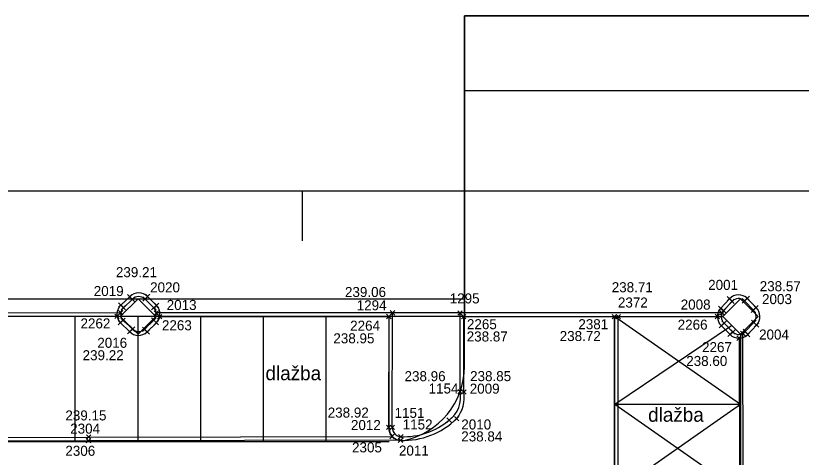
# Model space of a CAD drawing. Extents: x -264222 to -263676, y -1242344 to -1242060.
# Drawn here: x -264149.44 to -264118.14, y -1242197.1 to -1242179.48 of the extents above; entities that cross this region are included whole.
import ezdxf

# ---------------------------------------------------------------- set-up
doc = ezdxf.new("R2010")
doc.units = 0
for name, color, linetype in [('BODY_CISLO', 7, 'Continuous'), ('BODY_SYMBOL', 7, 'Continuous'), ('BODY_VYSKA', 7, 'Continuous'), ('KOORDINACNA_SITUACIA_DSP', 7, 'Continuous'), ('POPIS', 7, 'Continuous'), ('PROJEKT_DRS_OBRUBNIKY_KOMUNIKACIE', 7, 'Continuous'), ('PROJEKT_DRS_TDZ_VODOROVNE', 7, 'Continuous'), ('RAM_NA_TLAC_8xA4_1-200', 7, 'Continuous'), ('SO_20-3_OBRUBNIKY_DOLNA_HRANA', 7, 'Continuous'), ('SO_20-3_OBRUBNIKY_HORNA_HRANA', 7, 'Continuous')]:
    doc.layers.add(name, color=color, linetype=linetype)

msp = doc.modelspace()

# ---------------------------------------------------------------- linework, layer by layer
at = {"layer": 'BODY_SYMBOL'}
for p, q in [((-264144.989, -1242190.779), (-264144.813, -1242190.603)), ((-264144.813, -1242190.779), (-264144.989, -1242190.603)), ((-264144.276, -1242190.772), (-264144.1, -1242190.596)), ((-264144.1, -1242190.772), (-264144.276, -1242190.596)), ((-264144.884, -1242190.882), (-264144.708, -1242190.706)), ((-264144.708, -1242190.882), (-264144.884, -1242190.706)), ((-264144.38, -1242190.87), (-264144.204, -1242190.694)), ((-264144.204, -1242190.87), (-264144.38, -1242190.694)), ((-264121.093, -1242190.859), (-264120.917, -1242190.683)), ((-264120.917, -1242190.859), (-264121.093, -1242190.683)), ((-264120.993, -1242190.968), (-264120.817, -1242190.792)), ((-264120.817, -1242190.968), (-264120.993, -1242190.792)), ((-264120.494, -1242190.945), (-264120.318, -1242190.769)), ((-264120.318, -1242190.945), (-264120.494, -1242190.769)), ((-264120.384, -1242190.849), (-264120.208, -1242190.673)), ((-264120.208, -1242190.849), (-264120.384, -1242190.673)), ((-264145.346, -1242191.417), (-264145.17, -1242191.241)), ((-264145.17, -1242191.417), (-264145.346, -1242191.241)), ((-264145.341, -1242191.113), (-264145.165, -1242190.937)), ((-264145.165, -1242191.113), (-264145.341, -1242190.937)), ((-264145.238, -1242191.221), (-264145.062, -1242191.045)), ((-264145.062, -1242191.221), (-264145.238, -1242191.045)), ((-264144.028, -1242191.218), (-264143.852, -1242191.042)), ((-264143.852, -1242191.218), (-264144.028, -1242191.042)), ((-264143.919, -1242191.129), (-264143.743, -1242190.953)), ((-264143.743, -1242191.129), (-264143.919, -1242190.953)), ((-264121.442, -1242191.24), (-264121.266, -1242191.064)), ((-264121.266, -1242191.24), (-264121.442, -1242191.064)), ((-264121.328, -1242191.336), (-264121.152, -1242191.16)), ((-264121.152, -1242191.336), (-264121.328, -1242191.16)), ((-264120.142, -1242191.318), (-264119.966, -1242191.142)), ((-264119.966, -1242191.318), (-264120.142, -1242191.142)), ((-264120.033, -1242191.215), (-264119.857, -1242191.039)), ((-264119.857, -1242191.215), (-264120.033, -1242191.039)), ((-264145.491, -1242191.564), (-264145.315, -1242191.388)), ((-264145.315, -1242191.564), (-264145.491, -1242191.388)), ((-264145.252, -1242191.718), (-264145.076, -1242191.542)), ((-264145.076, -1242191.718), (-264145.252, -1242191.542)), ((-264144.029, -1242191.716), (-264143.853, -1242191.54)), ((-264143.853, -1242191.716), (-264144.029, -1242191.54)), ((-264143.928, -1242191.426), (-264143.752, -1242191.25)), ((-264143.752, -1242191.426), (-264143.928, -1242191.25)), ((-264143.794, -1242191.572), (-264143.618, -1242191.396)), ((-264143.618, -1242191.572), (-264143.794, -1242191.396)), ((-264134.664, -1242191.569), (-264134.488, -1242191.393)), ((-264134.488, -1242191.569), (-264134.664, -1242191.393)), ((-264134.518, -1242191.422), (-264134.342, -1242191.246)), ((-264134.342, -1242191.422), (-264134.518, -1242191.246)), ((-264131.826, -1242191.425), (-264131.65, -1242191.249)), ((-264131.65, -1242191.425), (-264131.826, -1242191.249)), ((-264131.68, -1242191.574), (-264131.504, -1242191.398)), ((-264131.504, -1242191.574), (-264131.68, -1242191.398)), ((-264125.678, -1242191.572), (-264125.502, -1242191.396)), ((-264125.502, -1242191.572), (-264125.678, -1242191.396)), ((-264125.523, -1242191.572), (-264125.347, -1242191.396)), ((-264125.347, -1242191.572), (-264125.523, -1242191.396)), ((-264121.573, -1242191.57), (-264121.397, -1242191.394)), ((-264121.397, -1242191.57), (-264121.573, -1242191.394)), ((-264121.386, -1242191.425), (-264121.21, -1242191.249)), ((-264121.21, -1242191.425), (-264121.386, -1242191.249)), ((-264145.361, -1242191.818), (-264145.185, -1242191.642)), ((-264145.185, -1242191.818), (-264145.361, -1242191.642)), ((-264143.927, -1242191.819), (-264143.751, -1242191.643)), ((-264143.751, -1242191.819), (-264143.927, -1242191.643)), ((-264121.422, -1242191.934), (-264121.246, -1242191.758)), ((-264121.246, -1242191.934), (-264121.422, -1242191.758)), ((-264121.306, -1242191.836), (-264121.13, -1242191.66)), ((-264121.13, -1242191.836), (-264121.306, -1242191.66)), ((-264120.122, -1242191.808), (-264119.946, -1242191.632)), ((-264119.946, -1242191.808), (-264120.122, -1242191.632)), ((-264120.016, -1242191.913), (-264119.84, -1242191.737)), ((-264119.84, -1242191.913), (-264120.016, -1242191.737)), ((-264144.995, -1242192.171), (-264144.819, -1242191.995)), ((-264144.819, -1242192.171), (-264144.995, -1242191.995)), ((-264144.877, -1242192.074), (-264144.701, -1242191.898)), ((-264144.701, -1242192.074), (-264144.877, -1242191.898)), ((-264144.397, -1242192.079), (-264144.221, -1242191.903)), ((-264144.221, -1242192.079), (-264144.397, -1242191.903)), ((-264144.294, -1242192.185), (-264144.118, -1242192.009)), ((-264144.118, -1242192.185), (-264144.294, -1242192.009)), ((-264121.072, -1242192.285), (-264120.896, -1242192.109)), ((-264120.896, -1242192.285), (-264121.072, -1242192.109)), ((-264120.955, -1242192.19), (-264120.779, -1242192.014)), ((-264120.779, -1242192.19), (-264120.955, -1242192.014)), ((-264120.563, -1242192.247), (-264120.387, -1242192.071)), ((-264120.387, -1242192.247), (-264120.563, -1242192.071)), ((-264120.463, -1242192.168), (-264120.287, -1242191.992)), ((-264120.287, -1242192.168), (-264120.463, -1242191.992)), ((-264120.365, -1242192.288), (-264120.189, -1242192.112)), ((-264120.189, -1242192.288), (-264120.365, -1242192.112)), ((-264120.712, -1242192.434), (-264120.536, -1242192.258)), ((-264120.536, -1242192.434), (-264120.712, -1242192.258)), ((-264131.827, -1242194.565), (-264131.651, -1242194.389)), ((-264131.651, -1242194.565), (-264131.827, -1242194.389)), ((-264131.678, -1242194.582), (-264131.502, -1242194.406)), ((-264131.502, -1242194.582), (-264131.678, -1242194.406)), ((-264132.26, -1242195.703), (-264132.084, -1242195.527)), ((-264132.084, -1242195.703), (-264132.26, -1242195.527)), ((-264131.963, -1242195.64), (-264131.787, -1242195.464)), ((-264131.787, -1242195.64), (-264131.963, -1242195.464)), ((-264134.674, -1242195.993), (-264134.498, -1242195.817)), ((-264134.498, -1242195.993), (-264134.674, -1242195.817)), ((-264134.526, -1242195.994), (-264134.35, -1242195.818)), ((-264134.35, -1242195.994), (-264134.526, -1242195.818)), ((-264146.62, -1242196.381), (-264146.444, -1242196.205)), ((-264146.444, -1242196.381), (-264146.62, -1242196.205)), ((-264134.536, -1242196.356), (-264134.36, -1242196.18)), ((-264134.36, -1242196.356), (-264134.536, -1242196.18)), ((-264134.186, -1242196.364), (-264134.01, -1242196.188)), ((-264134.01, -1242196.364), (-264134.186, -1242196.188)), ((-264146.629, -1242196.527), (-264146.453, -1242196.351)), ((-264146.453, -1242196.527), (-264146.629, -1242196.351)), ((-264134.199, -1242196.508), (-264134.023, -1242196.332)), ((-264134.023, -1242196.508), (-264134.199, -1242196.332))]:
    msp.add_line(p, q, dxfattribs=at)
at = {"layer": 'KOORDINACNA_SITUACIA_DSP'}
for p, q in [((-264131.568, -1242193.482), (-264131.568, -1242186.466)), ((-264131.568, -1242186.466), (-264131.568, -1242191.482)), ((-264170.162, -1242190.775), (-264131.568, -1242190.775)), ((-264131.568, -1242191.482), (-264172.558, -1242191.482)), ((-264134.568, -1242191.482), (-264169.568, -1242191.482)), ((-264134.568, -1242195.932), (-264134.568, -1242191.482)), ((-264120.568, -1242192.189), (-264120.568, -1242209.775))]:
    msp.add_line(p, q, dxfattribs=at)
for points in [[(-264144.568, -1242190.775), (-264143.861, -1242191.482), (-264144.568, -1242192.189), (-264145.275, -1242191.482)], [(-264120.568, -1242190.775), (-264119.861, -1242191.482), (-264120.568, -1242192.189), (-264121.275, -1242191.482)]]:
    msp.add_lwpolyline(points, close=True, dxfattribs=at)
msp.add_lwpolyline([(-264143.861, -1242191.482), (-264143.861, -1242191.482), (-264144.568, -1242192.189), (-264145.275, -1242191.482)], dxfattribs=at)
for centre, radius, start, end in [((-264134.568, -1242193.482), 3, 281.537, 0), ((-264134.068, -1242195.932), 0.5, 180, 281.537)]:
    msp.add_arc(centre, radius, start, end, dxfattribs=at)
at = {"layer": 'PROJEKT_DRS_OBRUBNIKY_KOMUNIKACIE'}
for p, q in [((-263959.468, -1242179.482), (-264131.568, -1242179.482)), ((-264131.568, -1242193.482), (-264131.568, -1242179.482)), ((-264077.23, -1242179.482), (-264131.568, -1242179.482)), ((-264131.568, -1242179.482), (-264131.568, -1242191.482)), ((-264131.568, -1242179.482), (-263959.468, -1242179.482)), ((-264045.204, -1242182.482), (-264131.568, -1242182.482)), ((-264170.162, -1242190.775), (-264131.568, -1242190.775)), ((-264131.568, -1242191.482), (-264172.558, -1242191.482)), ((-264134.568, -1242191.482), (-264169.568, -1242191.482)), ((-264134.568, -1242195.932), (-264134.568, -1242191.482)), ((-264131.568, -1242191.482), (-264121.275, -1242191.482)), ((-264125.568, -1242270.982), (-264125.568, -1242191.482)), ((-264120.568, -1242192.189), (-264120.568, -1242209.775)), ((-264134.568, -1242196.482), (-264170.068, -1242196.482))]:
    msp.add_line(p, q, dxfattribs=at)
for points in [[(-264144.568, -1242190.775), (-264143.861, -1242191.482), (-264144.568, -1242192.189), (-264145.275, -1242191.482), (-264144.568, -1242190.775)], [(-264120.568, -1242190.775), (-264119.861, -1242191.482), (-264120.568, -1242192.189), (-264121.275, -1242191.482), (-264120.568, -1242190.775)], [(-264143.861, -1242191.482), (-264144.568, -1242192.189), (-264145.275, -1242191.482)]]:
    msp.add_lwpolyline(points, dxfattribs=at)
for centre, radius, start, end in [((-264134.568, -1242193.482), 3, 281.537, 0), ((-264134.068, -1242195.932), 0.5, 180, 281.537)]:
    msp.add_arc(centre, radius, start, end, dxfattribs=at)
at = {"layer": 'PROJEKT_DRS_TDZ_VODOROVNE'}
for p, q in [((-264147.068, -1242196.482), (-264147.068, -1242191.482)), ((-264144.568, -1242196.482), (-264144.568, -1242191.482)), ((-264142.068, -1242196.482), (-264142.068, -1242191.482)), ((-264139.568, -1242196.482), (-264139.568, -1242191.482)), ((-264137.068, -1242196.482), (-264137.068, -1242191.482)), ((-264125.568, -1242191.482), (-264120.568, -1242194.982)), ((-264125.568, -1242194.982), (-264120.921, -1242191.836)), ((-264125.568, -1242194.982), (-264120.568, -1242194.982)), ((-264125.568, -1242194.982), (-264120.568, -1242198.482)), ((-264125.568, -1242198.482), (-264120.568, -1242194.982))]:
    msp.add_line(p, q, dxfattribs=at)
at = {"layer": 'RAM_NA_TLAC_8xA4_1-200'}
msp.add_line((-264138.03, -1242186.466), (-264138.03, -1242188.466), dxfattribs=at)
msp.add_lwpolyline([(-264222.03, -1242186.466), (-264054.03, -1242186.466), (-264054.03, -1242305.266), (-264222.03, -1242305.266)], close=True, dxfattribs=at)
at = {"layer": 'SO_20-3_OBRUBNIKY_DOLNA_HRANA'}
for p, q in [((-264145.253, -1242191.025), (-264144.901, -1242190.691)), ((-264144.188, -1242190.684), (-264143.831, -1242191.041)), ((-264121.354, -1242191.152), (-264121.005, -1242190.771)), ((-264120.296, -1242190.761), (-264119.945, -1242191.127)), ((-264153.705, -1242191.47), (-264145.403, -1242191.476)), ((-264144.907, -1242192.083), (-264145.273, -1242191.73)), ((-264143.839, -1242191.731), (-264144.206, -1242192.097)), ((-264120.984, -1242192.197), (-264121.334, -1242191.846)), ((-264119.928, -1242191.825), (-264120.277, -1242192.2)), ((-264120.624, -1242192.346), (-264120.576, -1242209.647))]:
    msp.add_line(p, q, dxfattribs=at)
for points in [[(-264143.706, -1242191.484), (-264134.576, -1242191.481), (-264134.586, -1242195.905)], [(-264131.59, -1242194.494), (-264131.592, -1242191.486), (-264121.485, -1242191.482)], [(-264125.573, -1242270.915), (-264125.578, -1242264.895), (-264125.575, -1242255.299), (-264125.581, -1242244.324), (-264125.582, -1242233.844), (-264125.584, -1242219.84), (-264125.593, -1242209.81), (-264125.59, -1242197.798), (-264125.59, -1242191.484)], [(-264125.429, -1242270.662), (-264125.437, -1242264.9), (-264125.431, -1242255.315), (-264125.435, -1242244.34), (-264125.439, -1242233.845), (-264125.44, -1242219.841), (-264125.448, -1242209.814), (-264125.447, -1242197.797), (-264125.435, -1242191.484)], [(-264134.111, -1242196.42), (-264146.541, -1242196.439), (-264159.053, -1242196.46), (-264170.082, -1242196.449)], [(-264169.718, -1242196.306), (-264159.062, -1242196.316), (-264146.532, -1242196.293), (-264134.448, -1242196.268)]]:
    msp.add_lwpolyline(points, dxfattribs=at)
for centre, major_axis, ratio, start_param, end_param in [((-264144.541, -1242191.035), (-0.422, -0.263), 0.999561, 3.365891, 4.96317), ((-264120.645, -1242191.116), (-0.299, 0.398), 0.999195, 4.861097, 6.446101), ((-264144.917, -1242191.387), (0.345, -0.354), 0.99993, 3.116184, 4.704475), ((-264144.191, -1242191.382), (-0.199, 0.454), 0.999498, 3.518922, 5.05719), ((-264120.987, -1242191.489), (-0.008, -0.498), 0.999493, 3.986167, 5.529115), ((-264120.286, -1242191.485), (0.366, 0.332), 0.999212, 4.786746, 6.357217), ((-264144.55, -1242191.732), (0.45, -0.222), 0.999046, 4.376126, 5.925508), ((-264120.629, -1242191.849), (0.492, -0.07), 0.999786, 4.058846, 5.64051), ((-264132.871, -1242194.716), (0.519, 1.193), 0.999825, 4.424596, 5.294154), ((-264133.978, -1242193.449), (1.173, -2.733), 0.999586, 5.832872, 6.663414), ((-264134.091, -1242195.924), (0.143, -0.475), 0.999359, 4.382247, 5.950366)]:
    msp.add_ellipse(centre, major_axis=major_axis, ratio=ratio, start_param=start_param, end_param=end_param, dxfattribs=at)
at = {"layer": 'SO_20-3_OBRUBNIKY_HORNA_HRANA'}
for p, q in [((-264145.15, -1242191.133), (-264144.796, -1242190.794)), ((-264144.292, -1242190.782), (-264143.94, -1242191.13)), ((-264120.905, -1242190.88), (-264121.24, -1242191.248)), ((-264120.054, -1242191.23), (-264120.406, -1242190.857)), ((-264153.851, -1242191.32), (-264145.258, -1242191.329)), ((-264134.43, -1242191.334), (-264143.84, -1242191.338)), ((-264134.438, -1242195.906), (-264134.43, -1242191.334)), ((-264131.738, -1242191.337), (-264134.43, -1242191.334)), ((-264131.739, -1242194.477), (-264131.738, -1242191.337)), ((-264121.298, -1242191.337), (-264131.738, -1242191.337)), ((-264144.789, -1242191.986), (-264145.164, -1242191.63)), ((-264143.941, -1242191.628), (-264144.309, -1242191.991)), ((-264120.867, -1242192.102), (-264121.218, -1242191.748)), ((-264120.034, -1242191.72), (-264120.375, -1242192.08)), ((-264120.432, -1242209.796), (-264120.475, -1242192.159))]:
    msp.add_line(p, q, dxfattribs=at)
for centre, major_axis, ratio, start_param, end_param in [((-264144.538, -1242191.045), (-0.315, -0.173), 0.999249, 3.457587, 5.009545), ((-264120.644, -1242191.112), (-0.018, -0.349), 0.999604, 2.442089, 4.03731), ((-264144.919, -1242191.388), (0.129, -0.32), 0.999189, 3.495291, 5.107355), ((-264144.191, -1242191.378), (-0.256, 0.243), 0.999863, 3.115121, 4.681209), ((-264120.288, -1242191.485), (0.177, 0.297), 0.998641, 4.503908, 6.079514), ((-264120.974, -1242191.487), (-0.005, -0.358), 0.99766, 3.996827, 5.544901), ((-264144.546, -1242191.729), (0.319, -0.151), 0.999204, 4.39641, 5.890386), ((-264120.631, -1242191.859), (0.338, -0.02), 0.999255, 4.002727, 5.632823), ((-264132.841, -1242194.709), (0.341, 1.074), 0.999027, 4.085727, 5.227258), ((-264133.993, -1242193.452), (2.311, -1.629), 0.99934, 5.28896, 6.025987), ((-264134.079, -1242195.917), (0.038, -0.357), 0.999322, 4.574758, 6.122971)]:
    msp.add_ellipse(centre, major_axis=major_axis, ratio=ratio, start_param=start_param, end_param=end_param, dxfattribs=at)

# ---------------------------------------------------------------- texts
at = {"layer": 'BODY_CISLO'}
for s, p in [('2019', (-264146.333, -1242190.665)), ('2020', (-264144.088, -1242190.517)), ('2001', (-264121.855, -1242190.42)), ('1295', (-264132.152, -1242190.96)), ('2003', (-264119.709, -1242190.986)), ('2013', (-264143.427, -1242191.22)), ('1294', (-264135.857, -1242191.234)), ('2372', (-264125.451, -1242191.123)), ('2008', (-264122.949, -1242191.205)), ('2262', (-264146.861, -1242191.957)), ('2263', (-264143.617, -1242192.031)), ('2264', (-264136.118, -1242192.047)), ('2265', (-264131.466, -1242191.988)), ('2381', (-264127.027, -1242191.989)), ('2266', (-264123.069, -1242192.006)), ('2004', (-264119.827, -1242192.401)), ('2016', (-264146.192, -1242192.73)), ('2267', (-264122.098, -1242192.903)), ('1154', (-264132.993, -1242194.553)), ('2009', (-264131.354, -1242194.559)), ('1151', (-264134.349, -1242195.525)), ('2012', (-264136.087, -1242196.011)), ('1152', (-264134.025, -1242195.988)), ('2010', (-264131.691, -1242195.988)), ('2304', (-264147.272, -1242196.154)), ('2305', (-264136.043, -1242196.902)), ('2306', (-264147.464, -1242197.038)), ('2011', (-264134.174, -1242197.029))]:
    msp.add_text(s, height=0.4, dxfattribs=at).set_placement(p)
at = {"layer": 'BODY_VYSKA'}
for s, p in [('239.21', (-264145.451, -1242189.913)), ('239.06', (-264136.325, -1242190.704)), ('238.71', (-264125.697, -1242190.513)), ('238.57', (-264119.801, -1242190.472)), ('238.95', (-264136.787, -1242192.551)), ('238.87', (-264131.474, -1242192.478)), ('238.72', (-264127.77, -1242192.46)), ('239.22', (-264146.777, -1242193.226)), ('238.60', (-264122.728, -1242193.454)), ('238.96', (-264133.951, -1242194.062)), ('238.85', (-264131.34, -1242194.06)), ('239.15', (-264147.463, -1242195.627)), ('238.92', (-264137.012, -1242195.514)), ('238.84', (-264131.692, -1242196.465))]:
    msp.add_text(s, height=0.4, dxfattribs=at).set_placement(p)
at = {"layer": 'POPIS'}
for p in [(-264139.491, -1242194.023), (-264124.246, -1242195.68)]:
    msp.add_text('dlažba', height=0.5625, rotation=360, dxfattribs=at).set_placement(p)

doc.saveas('drawing.dxf')
